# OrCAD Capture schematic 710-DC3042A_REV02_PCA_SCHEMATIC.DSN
size B; company: ANALOG DEVICES
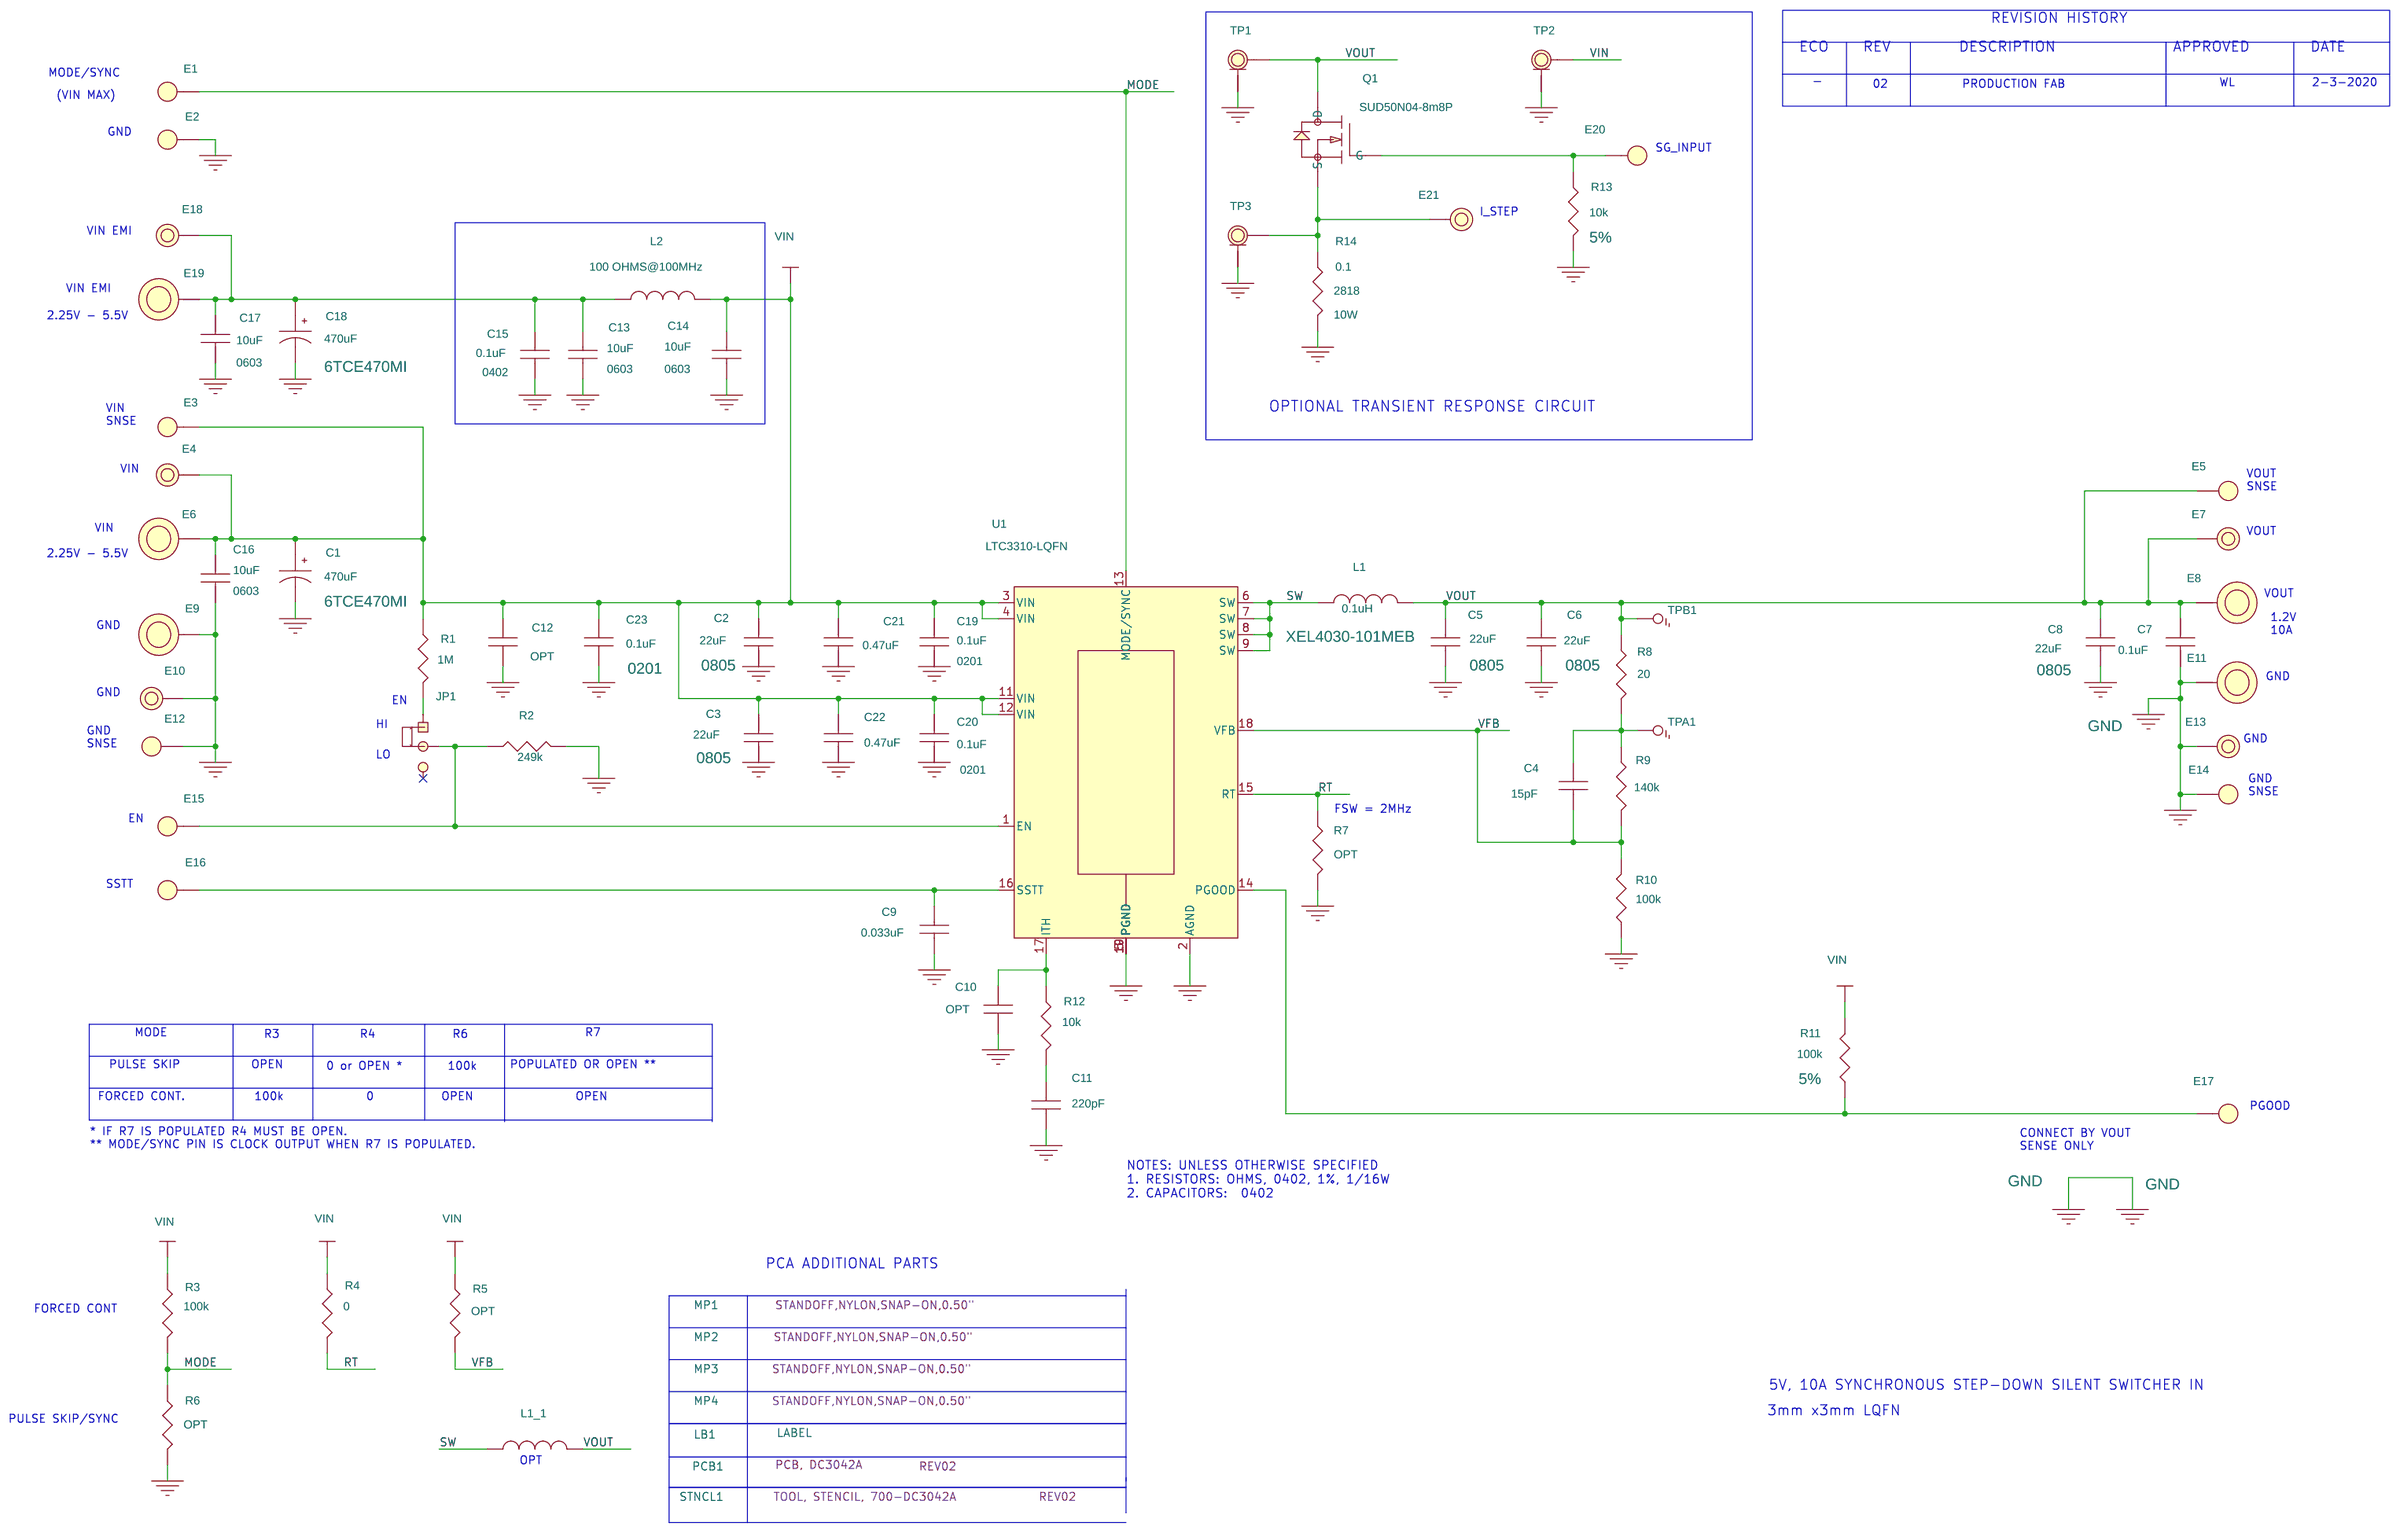
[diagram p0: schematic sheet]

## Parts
C1  470uF  [CAPMP7343N]
C2  22uF  [CC0805N]
C3  22uF  [CC0805N]
C4  15pF  [CC0402N]
C5  22uF  [CC0805N]
C6  22uF  [CC0805N]
C7  0.1uF  [CC0402N]
C8  22uF  [CC0805N]
C9  0.033uF  [CC0402N]
C10  OPT  [CC0402N]
C11  220pF  [CC0402N]
C12  OPT  [CC0402N]
C13  10uF  [CC0603N]
C14  10uF  [CC0603N]
C15  0.1uF  [CC0402N]
C16  10uF  [CC0603N]
C17  10uF  [CC0603N]
C18  470uF  [CAPMP7343N]
C19  0.1uF  [CC0201M]
C20  0.1uF  [CC0201M]
C21  0.47uF  [CC0402N]
C22  0.47uF  [CC0402N]
C23  0.1uF  [CC0201M]
E1  TEST POINT  [MILLMAX2308]
E2  TEST POINT  [MILLMAX2308]
E3  TEST POINT  [MILLMAX2308]
E4  TEST POINT  [MILLMAX2501]
E5  TEST POINT  [MILLMAX2308]
E6  BANANA JACK  [KEY-575-4]
E7  TEST POINT  [MILLMAX2501]
E8  BANANA JACK  [KEY-575-4]
E9  BANANA JACK  [KEY-575-4]
E10  TEST POINT  [MILLMAX2501]
E11  BANANA JACK  [KEY-575-4]
E12  TEST POINT  [MILLMAX2308]
E13  TEST POINT  [MILLMAX2501]
E14  TEST POINT  [MILLMAX2308]
E15  TEST POINT  [MILLMAX2308]
E16  TEST POINT  [MILLMAX2308]
E17  TEST POINT  [MILLMAX2308]
E18  TEST POINT  [MILLMAX2501]
E19  BANANA JACK  [KEY-575-4]
E20  TEST POINT  [MILLMAX2308]
E21  TEST POINT  [MILLMAX2501]
JP1  HDR  [HD1X3-079]
L1  0.1uH  [COILCRAFT-XEL4030]
L1_1  72nH  [COILCRAFT-XEL3515]
L2  100 OHMS@100MHz  [WURTH-74279226101]
LB1  LABEL  [895-0154_REV01]
MP1  STANDOFF  [KEYSTONE_8829-8834]
MP2  STANDOFF  [KEYSTONE_8829-8834]
MP3  STANDOFF  [KEYSTONE_8829-8834]
MP4  STANDOFF  [KEYSTONE_8829-8834]
PCB1  PCB, DC3042A
Q1  SUD50N04-8m8P  [TO-252-3N]
R1  1M  [CR0402N]
R2  249k  [CR0402N]
R3  100k  [CR0402N]
R4  0  [CR0402N]
R5  OPT  [CR0402N]
R6  OPT  [CR0402N]
R7  OPT  [CR0402N]
R8  20  [CR0402N]
R9  140k  [CR0402N]
R10  100k  [CR0402N]
R11  100k  [CR0402N]
R12  10k  [CR0402N]
R13  10k  [CR0402N]
R14  0.1  [VISHAY-WSHP2818]
STNCL1  TOOL, STENCIL, 700-DC3042A
TP1  TEST JACK  [HODEN-PA-652_ALT1]
TP2  TEST JACK  [HODEN-PA-652_ALT1]
TP3  TEST JACK  [HODEN-PA-652_ALT1]
TPA1  COPPER FEATURE PAD  [PADSTYLE1]
TPB1  COPPER FEATURE PAD  [PADSTYLE1]
U1  LTC3310-LQFN  [LTC-LQFN-18-1548]
XJP4  SHUNT

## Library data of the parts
C1 C18 = CAP_P_ALT: CAP.,470uF,TANT POLY,6.3V,20%,7343; CLASS: DISCRETE; Dielectric Type: TANT POLY; Inventory Qty: 0; Manufacturer: PANASONIC; Manufacturer PN: 6TCE470MI; PART_NUMBER: 150-0805; Package Size: 7343; Package Type: Surface Mount; Rated Voltage: 6.3V; Tolerance: 20%
C2 C3 C5 C6 C8 = CAP: CAP.,22uF,X7S,6.3V,20%,0805; CLASS: DISCRETE; Dielectric Type: X7S; Inventory Qty: 0; Manufacturer: TDK; Manufacturer PN: C2012X7S0J226M125AC; PART_NUMBER: 150-0806; Package Size: 0805; Rated Voltage: 6.3V; Temperature Coefficient: X7S; Tolerance: 20%
C4 = CAP: CAP.,15pF,C0G/NP0,50V,5%,0402; CLASS: DISCRETE; Dielectric Type: C0G/NP0; FPLIST: CC0402N,CC0402L,CC0402M; Inventory Qty: 20360; Manufacturer: AVX; Manufacturer PN: 04025A150JAT2A; PART_NUMBER: 150-2491; Package Size: 0402; Rated Voltage: 50V; Tolerance: 5%
C7 C15 = CAP: CAP.,0.1uF,X7R,50V,10%,0402,AEC-Q200; CLASS: DISCRETE; Dielectric Type: X7R; FPLIST: CC0402N,CC0402L,CC0402M; Inventory Qty: 51770; Manufacturer: MURATA; Manufacturer PN: GCM155R71H104KE02D; PART_NUMBER: 150-2620; Package Size: 0402; Rated Voltage: 50V; Temperature Coefficient: X7R; Tolerance: 10%
C9 = CAP: CAP.,0.033uF,X7R,25V,10%,0402; CLASS: DISCRETE; Dielectric Type: X7R; FPLIST: CC0402N,CC0402L,CC0402M; Inventory Qty: 29274; Manufacturer: KEMET; Manufacturer PN: C0402C333K3RACTU; PART_NUMBER: 150-0484; Package Size: 0402; Rated Voltage: 25V; Tolerance: 10%
C10 = CAP: CAP., OPTION, 0402; CLASS: DISCRETE; PART_NUMBER: 150-3148; Package Size: 0402; Package Type: SMD
C11 = CAP: CAP.,220pF,C0G,50V,5%,0402; CLASS: DISCRETE; Dielectric Type: C0G; FPLIST: CC0402N,CC0402L,CC0402M; Inventory Qty: 50535; Manufacturer: AVX; Manufacturer PN: 04025A221JAT2A; PART_NUMBER: 150-2013; Package Size: 0402; Rated Voltage: 50V; Tolerance: 5%
C12 = CAP: CAP., OPTION, 0402; CLASS: DISCRETE; FPLIST: CC0402N,CC0402L,CC0402M; PART_NUMBER: 150-3148; Package Size: 0402; Package Type: SMD
C13 C14 C16 C17 = CAP: CAP.,10uF,X7S,6.3V,20%,0603; CLASS: DISCRETE; Dielectric Type: X7S; FPLIST: CC0603N,CC0603L,CC0603M; Inventory Qty: 21400; Manufacturer: TDK; Manufacturer PN: C1608X7S0J106M080AC; PART_NUMBER: 150-1745; Package Size: 0603; Rated Voltage: 6.3V; Tolerance: 20%
C19 C20 = CAP: CAP.,0.1uF,X7S,16V,10%,0201; CLASS: DISCRETE; Dielectric Type: X7S; FPLIST: CC0201N,CC0201L,CC0201M; Inventory Qty: 30000; Manufacturer: MURATA; Manufacturer PN: GRM033C71C104KE14D; PART_NUMBER: 150-0807; Package Size: 0201; Rated Voltage: 16V; Temperature Coefficient: X7S; Tolerance: 10%
C21 C22 = CAP: CAP.,0.47uF,X7S,10V,10%,0402,AEC-Q200; CLASS: DISCRETE; Dielectric Type: X7S; FPLIST: CC0402N,CC0402L,CC0402M; Inventory Qty: 8200; Manufacturer: MURATA; Manufacturer PN: GCM155C71A474KE36D; PART_NUMBER: 150-1786; Package Size: 0402; Package Type: SMD/SMT; Rated Voltage: 10V; Tolerance: 10%
C23 = CAP: CAP.,0.1uF,X7S,16V,10%,0201; CLASS: DISCRETE; Dielectric Type: X7S; Inventory Qty: 30000; Manufacturer: MURATA; Manufacturer PN: GRM033C71C104KE14D; PART_NUMBER: 150-0807; Package Size: 0201; Rated Voltage: 16V; Temperature Coefficient: X7S; Tolerance: 10%
E1-E3 E5 E12 E14-E17 E20 = TEST_POINT_.156_MILL-MAX_2308: TEST POINT,TURRET,0.064" MTG. HOLE,PCB 0.062" THK; CLASS: IO; Inventory Qty: 682175; Manufacturer PN: 2308-2-00-80-00-00-07-0; PART_NUMBER: 260-0004
E4 E7 E10 E13 E18 = TESTPOINT_.219_MILL-MAX_2501: TEST POINT,TURRET,0.094" MTG. HOLE,PCB 0.062" THK; CLASS: IO; Inventory Qty: 377385; Manufacturer: MILL-MAX; Manufacturer PN: 2501-2-00-80-00-00-07-0; PART_NUMBER: 260-0003
E6 E8 E9 E11 E19 = BANANA_KEYSTONE-575-4: CONN.,BANANA JACK,FEMALE,THT,NON-INSULATED,SWAGE,0.218"; CLASS: IO; Inventory Qty: 171822; Manufacturer: KEYSTONE; Manufacturer PN: 575-4; PART_NUMBER: 250-0428
E21 = TESTPOINT_.219_MILL-MAX_2501: TEST POINT,TURRET,0.094" MTG. HOLE,PCB 0.062" THK; CLASS: IO; FPLIST: MILLMAX2501,MILLMAX2501_ALT1; Inventory Qty: 377385; Manufacturer: MILL-MAX; Manufacturer PN: 2501-2-00-80-00-00-07-0; PART_NUMBER: 260-0003
JP1 = 3_PIN_HEADER_.079_SINGLE_ROW_D: CONN.,HDR,MALE,1x3,2mm,VERT,ST,THT; CLASS: IO; Inventory Qty: 24592; Manufacturer: Wurth Elektronik; Manufacturer PN: 62000311121; PART_NUMBER: 250-0484
L1 = IND_ALT: IND.,0.1uH,PWR,SHIELDED,20%,25.8A,1.8mOhms,4.3x4.3mm,XEL4030,AEC-Q200; CLASS: DISCRETE; Inventory Qty: 2550; Manufacturer: COILCRAFT; Manufacturer PN: XEL4030-101MEB; PART_NUMBER: 200-0670; Package Size: 4.3x4.3mm,XEL4030; Tolerance: 20%
L1_1 = IND_ALT: IND.,72nH,PWR,20%,23.6A,3.15mOHMS,3.2mmX3.5mm,AEC-Q200; CLASS: DISCRETE; Inventory Qty: 1392; Manufacturer: Coilcraft; Manufacturer PN: XEL3515-720MEB; PART_NUMBER: 200-0450; Package Size: 3.2mmX3.5mm; Tolerance: 20%
L2 = IND_ALT: IND.,100 OHMS@100MHz,FERRITE BEAD,25%,8A,6mOHMS,1812; CLASS: DISCRETE; Inventory Qty: 2492; Manufacturer: WURTH ELEKTRONIK; Manufacturer PN: 74279226101; PART_NUMBER: 200-0280; Package Size: 1812; Tolerance: 25%
LB1 = BLANK_LABEL: LABEL SPEC, DEMO BOARD SERIAL NUMBER; Inventory Qty: 0; Manufacturer: BRADY; Manufacturer PN: THT-96-717-10; PART_NUMBER: 895-0154
MP1-MP4 = BLANK_MECHANICAL_PART: STANDOFF,NYLON,SNAP-ON,0.50"; CLASS: DISCRETE; FPLIST: KEYSTONE_8829-8834,MTG-8831; Inventory Qty: 178182; Manufacturer: KEYSTONE; Manufacturer PN: 8833; PART_NUMBER: 763-0007
PCB1 = BLANK_PCB_PART: BOM Notes: REV02; CLASS: DISCRETE; Inventory Qty: 0; Manufacturer: MAO BANG; Manufacturer PN: 600-DC3042A; PART_NUMBER: 600-DC3042A
Q1 = 3P_N-CH_TYPE2A: XSTR.,MOSFET,N-CH,40V,14A,DPAK (TO-252); CLASS: DISCRETE; FPLIST: TO-252-3N,TO-252-3L,TO-252-3M; Inventory Qty: 40938; Manufacturer: VISHAY; Manufacturer PN: SUD50N04-8M8P-4GE3; PART_NUMBER: 240-0021; Package Type: DPAK (TO-252); Rated Voltage: 40V
R1 = RES: RES.,1M OHMS,1%,1/16W,0402,AEC-Q200; CLASS: DISCRETE; FPLIST: CR0402N,CR0402L,CR0402M; Inventory Qty: 90169; Manufacturer: STACKPOLE ELECTRONICS, INC.; Manufacturer PN: RMCF0402FT1M00; PART_NUMBER: 100-2457; Package Size: 0402; Rated Power: 1/16W; Temperature Coefficient: 100ppm; Tolerance: 1%
R2 = RES: RES.,249k OHMS,1%,1/16W,0402,AEC-Q200; CLASS: DISCRETE; FPLIST: CR0402N,CR0402L,CR0402M; Inventory Qty: 28050; Manufacturer: NIC; Manufacturer PN: NRC04F2493TRF; PART_NUMBER: 100-2663; Package Size: 0402; Rated Power: 1/16W; Temperature Coefficient: 100ppm; Tolerance: 1%
R3 R11 = RES: RES.,100k OHMS,5%,1/16W,0402,AEC-Q200; CLASS: DISCRETE; FPLIST: CR0402N,CR0402L,CR0402M; Inventory Qty: 44356; Manufacturer: NIC; Manufacturer PN: NRC04J104TRF; PART_NUMBER: 100-0359; Package Size: 0402; Rated Power: 1/16W; Temperature Coefficient: 200ppm/C; Tolerance: 5%
R4 = RES: RES.,0 OHM,1/16W,0402,AEC-Q200; CLASS: DISCRETE; FPLIST: CR0402N,CR0402L,CR0402M; Inventory Qty: 110814; Manufacturer: NIC; Manufacturer PN: NRC04ZOTRF; PART_NUMBER: 100-2023; Package Size: 0402; Rated Power: 1/16W
R5-R7 = RES: RES., OPTION, 0402; CLASS: DISCRETE; FPLIST: CR0402N,CR0402L,CR0402M; PART_NUMBER: 100-0357; Package Size: 0402
R8 = RES: RES.,20 OHMS,1%,1/16W,0402,AEC-Q200; CLASS: DISCRETE; FPLIST: CR0402N,CR0402L,CR0402M; Inventory Qty: 32382; Manufacturer: NIC; Manufacturer PN: NRC04F20R0TRF; PART_NUMBER: 100-0250; Package Size: 0402; Rated Power: 1/16W; Temperature Coefficient: 100ppm; Tolerance: 1%
R9 = RES: RES.,140k OHMS,1%,1/16W,0402,AEC-Q200; CLASS: DISCRETE; FPLIST: CR0402N,CR0402L,CR0402M; Inventory Qty: 71764; Manufacturer: NIC; Manufacturer PN: NRC04F1403TRF; PART_NUMBER: 100-2880; Package Size: 0402; Rated Power: 1/16W; Temperature Coefficient: 100ppm; Tolerance: 1%
R10 = RES: RES.,100k OHMS,1%,1/16W,0402,AEC-Q200; CLASS: DISCRETE; FPLIST: CR0402N,CR0402L,CR0402M; Inventory Qty: 153378; Manufacturer: VISHAY; Manufacturer PN: CRCW0402100KFKED; PART_NUMBER: 100-2396; Package Size: 0402; Rated Power: 1/16W; Temperature Coefficient: 100ppm; Tolerance: 1%
R12 = RES: RES.,10k OHMS,1%,1/16W,0402,AEC-Q200; CLASS: DISCRETE; FPLIST: CR0402N,CR0402L,CR0402M; Inventory Qty: 80516; Manufacturer: VISHAY; Manufacturer PN: CRCW040210K0FKED; PART_NUMBER: 100-2545; Package Size: 0402; Rated Power: 1/16W; Temperature Coefficient: 100ppm/C; Tolerance: 1%
R13 = RES: RES.,10k OHMS,5%,1/16W,0402,AEC-Q200; CLASS: DISCRETE; Inventory Qty: 69954; Manufacturer: NIC; Manufacturer PN: NRC04J103TRF; PART_NUMBER: 100-0214; Package Size: 0402; Rated Power: 1/16W; Temperature Coefficient: 200ppm; Tolerance: 5%
R14 = RES: RES.,0.1 OHM,1%,10W,2818,HIGH PWR,METAL,SENSE,AEC-Q200; CLASS: DISCRETE; Inventory Qty: 11250; Manufacturer: VISHAY; Manufacturer PN: WSHP2818R1000FEA; PART_NUMBER: 100-1262; Package Size: 2818; Rated Power: 10W; Temperature Coefficient: +/-75ppm; Tolerance: 1%
STNCL1 = BLANK_STENCIL_PART: BOM Notes: REV02; CLASS: DISCRETE; Inventory Qty: 0; Manufacturer: ANALOG DEVICES; Manufacturer PN: 830-DC3042A; PART_NUMBER: 830-DC3042A
TP1-TP3 = HODEN_TEST_JACK_PK5-2.5MM-113_1: CONN.,TEST JACK,PLUG,VERT. THT,SHIELDED, 1 POS; CLASS: IO; FPLIST: HODEN-PA-652, HODEN-PA-652_ALT1; Manufacturer: HODEN ELECTRONICS CO; Manufacturer PN: PK5-2.5MM-113; PART_NUMBER: TMP-3717
TPA1 TPB1 = PAD_SMALL_FILLED: TESTPOINT, PCB COPPER FEATURE; CLASS: IO; Manufacturer: N/A; Manufacturer PN: N/A; PART_NUMBER: PCBPADS-11
U1 = LTC3310-LQFN: IC,Low Voltage Syn. Stepdown Reg.,LQFN-18,10A; CLASS: IC; Inventory Qty: 0; Manufacturer: LINEAR TECH.; Manufacturer PN: LTC3310HV#PBF; PART_NUMBER: LTC3310HV#PBF; Package Size: 18-LQFN; Package Type: 18-pin LQFN
XJP4 = CONN_SHUNT_2_POS_2mm: CONN.,SHUNT,FEMALE,2 POS,2mm; CLASS: IO; Inventory Qty: 70216; Manufacturer: Wurth Elektronik; Manufacturer PN: 60800213421; PART_NUMBER: 250-0485

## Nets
GND: C1.2 C2.2 C3.2 C5.2 C6.2 C7.2 C8.2 C9.2 C10.2 C11.2 C12.2 C13.2 C14.2 C15.2 C16.2 C17.2 C18.2 C19.2 C20.2 C21.2 C22.2 C23.2 E2.1(A) E9.1 E10.1 E11.1 E12.1(A) E13.1 E14.1(A) R2.2 R6.2 R7.2 R10.1 R13.2 R14.2 TP1.2(GND) TP1.3(GND) TP1.4(GND) TP1.5(GND) TP2.2(GND) TP2.3(GND) TP2.4(GND) TP2.5(GND) TP3.2(GND) TP3.3(GND) TP3.4(GND) TP3.5(GND) U1.2(AGND) U1.5(PGND) U1.10(PGND) U1.19(PGND)
VIN: C1.1 C2.1 C3.1 C12.1 C14.1 C16.1 C19.1 C20.1 C21.1 C22.1 C23.1 E3.1(A) E4.1 E6.1 L2.2 R1.1 R3.1 R4.1 R5.1 R11.1 TP2.1 U1.3(VIN) U1.4(VIN) U1.11(VIN) U1.12(VIN)
MODE: E1.1(A) R3.2 R6.1 U1.13(MODE/SYNC)
RT: R4.2 R7.1 U1.15(RT)
SW: L1.1 L1_1.1 U1.6(SW) U1.7(SW) U1.8(SW) U1.9(SW)
VFB: C4.2 R5.2 R9.2 R10.2 U1.18(VFB)
VOUT: C5.1 C6.1 C7.1 C8.1 E5.1(A) E7.1 E8.1 L1.2 L1_1.2 Q1.2(D) R8.1 TP1.1 TPB1.1
N16777546: E15.1(A) JP1.2 R2.1 U1.1(EN)
N16777612: C4.1 R8.2 R9.1 TPA1.1
N16777640: E17.1(A) R11.2 U1.14(PGOOD)
N16777648: C10.1 R12.1 U1.17(ITH)
N16777650: C11.1 R12.2
N16777742: JP1.1 R1.2
N16777770: C9.1 E16.1(A) U1.16(SSTT)
N16814255: C13.1 C15.1 C17.1 C18.1 E18.1 E19.1 L2.1
N16841248: E20.1(A) Q1.1(G) R13.1
N16841255: E21.1 Q1.3(S) R14.1 TP3.1

Not connected (* = marked no-connect by the designer): JP1 3*

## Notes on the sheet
- REVISION HISTORY
- ECO
- REV
- DESCRIPTION
- APPROVED
- DATE
- MODE/SYNC
- -
- WL
- 2-3-2020
- (VIN MAX)
- 02
- PRODUCTION FAB
- GND
- SG_INPUT
- I_STEP
- VIN EMI
- VIN EMI
- 2.25V - 5.5V
- VIN
  SNSE
- OPTIONAL TRANSIENT RESPONSE CIRCUIT
- VIN
- VOUT
  SNSE
- VIN
- VOUT
- 2.25V - 5.5V
- VOUT
- GND
- 1.2V
  10A
- GND
- GND
- EN
- GND
  SNSE
- HI
- GND
- LO
- GND
  SNSE
- FSW = 2MHz
- EN
- SSTT
- MODE
- R3
- R4
- R6
- R7
- PULSE SKIP
- OPEN
- 0 or OPEN *
- 100k
- POPULATED OR OPEN **
- FORCED CONT.
- 100k
- 0
- OPEN
- OPEN
- PGOOD
- * IF R7 IS POPULATED R4 MUST BE OPEN.
  ** MODE/SYNC PIN IS CLOCK OUTPUT WHEN R7 IS POPULATED.
- CONNECT BY VOUT
  SENSE ONLY
- NOTES: UNLESS OTHERWISE SPECIFIED
  1. RESISTORS: OHMS, 0402, 1%, 1/16W
  2. CAPACITORS:  0402
- PCA ADDITIONAL PARTS
- FORCED CONT
- 5V, 10A SYNCHRONOUS STEP-DOWN SILENT SWITCHER IN
- PULSE SKIP/SYNC
- 3mm x3mm LQFN
- OPT
